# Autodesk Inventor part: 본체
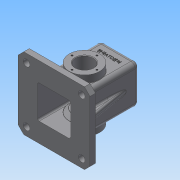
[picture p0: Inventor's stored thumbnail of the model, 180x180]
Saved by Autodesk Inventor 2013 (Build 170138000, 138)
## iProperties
Created: 2016-02
Part Number: 본체
Material: 일반
Document SubType Name: Modeling
Designer: Administrator
Density: 1 g/cm^3
Author: Administrator
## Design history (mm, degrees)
sketch "스케치1"
  geometry: L1 (35, -35)-(-35, -35); L2 (-35, -35)-(-35, 35); L3 (-35, 35)-(35, 35); L4 (35, 35)-(35, -35); L5 (35, -35)-(-35, 35); L6 (-35, -35)-(35, 35); 1 further point
  constraints: 12 end point, 2 midpoint, 2 parallel, 1 horizontal, 1 perpendicular
  dimensions: "d0" = 70 distance of L2.end L3.end; "d1" = 70 distance of L1.end L2.end
extrude "돌출1" new body sketch "스케치1" distance "d2" = 65; taper "d4" = 0 deg; dims "d3" = 55, "d5" = 0
fillet "모깎기1" dims "d6" = 8
fillet "모깎기2" dims "d7" = 8
feature "쉘1" dims "d8" = 5
sketch "스케치2"
  geometry: L1 (-27, -35)-(27, -35) reference; L2 (35, -27)-(35, 27) reference; L3 (27, 35)-(-27, 35) reference; L4 (-35, 27)-(-35, -27) reference; L5 (-65, 65)-(65, 65); L6 (65, 65)-(65, -65); L7 (65, -65)-(-65, -65); L8 (-65, -65)-(-65, 65); L9 (-65, 65)-(65, -65); L10 (65, 65)-(-65, -65); A1 r 8 centre (-27, -27) between (-35, -27) and (-27, -35) reference; A2 r 8 centre (27, -27) between (27, -35) and (35, -27) reference; A3 r 8 centre (27, 27) between (35, 27) and (27, 35) reference; A4 r 8 centre (-27, 27) between (-27, 35) and (-35, 27) reference; 1 further point
  constraints: 12 end point, 2 midpoint, 2 parallel, 1 horizontal, 1 perpendicular
  dimensions: "d9" = 130 distance of L6.end L7.end; "d10" = 130 distance of L5.end L6.end
extrude "돌출2" join sketch "스케치2" distance "d11" = 10; taper "d12" = 0 deg
sketch "스케치3"
  geometry: C1 r 27.5 at (27, -57); 1 further point
  constraints: 1 centre point, 1 coincident
  dimensions: "d13" = 55 diameter of C1
extrude "돌출3" join sketch "스케치3" distance "d14" = 13; taper "d15" = 0 deg
sketch "스케치4"
  geometry: C1 r 27.5 at (27, -57); 1 further point
  constraints: 1 centre point, 1 coincident
  dimensions: "d16" = 55 diameter of C1
extrude "돌출4" join sketch "스케치4" distance "d17" = 7; taper "d18" = -45 deg
sketch "스케치5"
  geometry: C1 r 20 at (0, 0); 1 further point
  constraints: 1 centre point, 1 coincident
  dimensions: "d19" = 40 diameter of C1
extrude "돌출5" join sketch "스케치5" distance "d20" = 10; taper "d21" = -10 deg
sketch "스케치7"
  geometry: C1 r 27.5 at (0, 0) reference; C2 r 16 at (0, 0)
  constraints: 1 centre point, 1 coincident
  dimensions: "d25" = 32 diameter of C2
extrude "돌출7" cut sketch "스케치7" stored distance "d26" = 10; taper "d27" = 0 deg
fillet "모깎기3" dims "d28" = 0.5
chamfer "모따기1" distance "d29" = 1; stored, may be unused: second distance "d30" = 2, angle "d31" = 45 deg
fillet "모깎기4" dims "d32" = 0.5
fillet "모깎기5" dims "d33" = 3
sketch "스케치8"
  geometry: L1 (65, -55)-(65, -45) reference; L2 (65, -45)-(-65, -45) reference; L3 (50, -45)-(35, 40.069); L4 (50, -45)-(150.19, -45); L5 (35, 57)-(35, -45) reference; 1 further point
  constraints: 4 end point, 2 point on line, 1 horizontal
  dimensions: "d34" = 100 deg angle of L4 L3; "d35" = 15 distance of L1.end L3.start
feature "리브1" sketch "스케치8" dims "d36" = 1, "d37" = 10, "d38" = 0, "d39" = 0, "d40" = 1, "d41" = 1
fillet "모깎기6" dims "d42" = 3
fillet "모깎기7" dims "d43" = 3
chamfer "모따기2" distance "d44" = 10; stored, may be unused: second distance "d45" = 2, angle "d46" = 45 deg
sketch "스케치9"
  geometry: L1 (55, 65)-(-55, 65) reference; L2 (65, -55)-(65, 55) reference; 2 further points
  dimensions: "d47" = 15 distance from line of L2 point (50, 50); "d48" = 15 distance from line of L1 point (50, 50)
hole "구멍1" sketch "스케치9" at (50, 50) diameter "d49" = 12; stored, may be unused: countersink angle "d53" = 90 deg, drill point angle "d55" = 118 deg; dims "d50" = 6, "d51" = 4, "d52" = 2, "d54" = 8
fillet "모깎기8" dims "d59" = 3
sketch "스케치10"
  geometry: C1 r 27.5 at (0, 0) reference; 1 further point
  constraints: 1 vertical alignment
  dimensions: "d60" = 22.5 distance of C1.centre point (0, 22.5)
hole "구멍2" sketch "스케치10" at (0, 22.5) diameter "d61" = 3.242; stored, may be unused: countersink angle "d65" = 90 deg, drill point angle "d67" = 118 deg; dims "d62" = 8, "d63" = 4, "d64" = 2, "d66" = 10
hole "구멍3" diameter "d73" = 21; stored, may be unused: countersink angle "d77" = 90 deg, drill point angle "d79" = 118 deg; dims "d71" = 10, "d72" = 10, "d74" = 8, "d75" = 28, "d76" = 4, "d78" = 10
sketch "스케치11"
  geometry: L1 (62, -99)-(62, 0) reference; L2 (8.763, 18)-(45.237, 18) reference; 1 further point
  constraints: 1 other
  dimensions: "d80" = 35 distance from line of L1 point (27, -12); "d81" = 30 distance from line of L2 point (27, -12)
feature "엠보싱1" sketch "스케치11" dims "d0" = 70, "d1" = 70, "d82" = 0.5, "d83" = 0
node "솔리드1"
mirror "대칭1"
mirror "대칭2"
mirror "대칭3"
pattern_circular "원형 패턴1" dims angle "d57" = 360 deg
pattern_circular "원형 패턴2" dims angle "d69" = 360 deg
mirror "대칭4"
